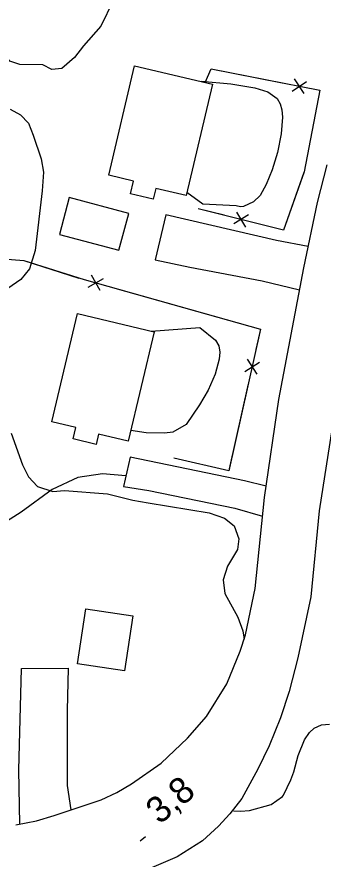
# Model space of a CAD drawing. Extents: x 282461 to 284471, y 5554090 to 5557646.
# Drawn here: x 283239.1 to 283274.2, y 5555299.8 to 5555396.4 of the extents above; entities that cross this region are included whole.
import ezdxf

# ---------------------------------------------------------------- set-up
doc = ezdxf.new("R2010")
doc.units = 0
for name, color, linetype in [('Niveau 1', 7, 'Continuous'), ('Niveau 19', 7, 'Continuous'), ('Niveau 2', 7, 'Continuous'), ('Niveau 21', 7, 'Continuous'), ('Niveau 22', 7, 'Continuous'), ('Niveau 3', 7, 'Continuous'), ('Niveau 31', 7, 'Continuous'), ('Niveau 37', 7, 'Continuous')]:
    doc.layers.add(name, color=color, linetype=linetype)

msp = doc.modelspace()

# ---------------------------------------------------------------- linework, layer by layer
at = {"layer": 'Niveau 1'}
for points in [[(283260.2, 5555389.04), (283263.57, 5555388.73), (283266.32, 5555388.27), (283267.84, 5555387.82), (283268.9, 5555387.04), (283269.24, 5555386.45), (283269.43, 5555385.74), (283269.52, 5555384.92), (283269.33, 5555383.01), (283268.93, 5555380.87), (283268.32, 5555378.87), (283267.64, 5555377.17), (283266.95, 5555375.94), (283266.19, 5555375.2), (283265.02, 5555374.66), (283264.68, 5555374.62), (283264.2, 5555374.76), (283260.36, 5555374.94), (283258.55, 5555376.27)], [(283254.45, 5555360.37), (283260.02, 5555360.79), (283261.84, 5555359.33), (283262.19, 5555358.68), (283262.31, 5555357.96), (283262.26, 5555357.16), (283261.8, 5555355.43), (283260.98, 5555353.59), (283260.01, 5555351.9), (283258.46, 5555349.66), (283256.94, 5555348.78), (283256, 5555348.65), (283253.9, 5555348.71), (283252.11, 5555348.98)]]:
    msp.add_lwpolyline(points, dxfattribs=at)
at = {"layer": 'Niveau 19'}
for points in [[(283272.45, 5555370.07), (283268.81, 5555370.77), (283256.13, 5555373.7), (283254.92, 5555368.53), (283258.87, 5555367.7), (283267.19, 5555366.12), (283271.45, 5555365.11)], [(283267.63, 5555342.57), (283265.16, 5555343.18), (283252.06, 5555345.92), (283251.29, 5555342.55), (283254.2, 5555342.06), (283264.04, 5555340.04), (283267.2, 5555339.13)], [(283239.41, 5555303.82), (283239.29, 5555310), (283239.61, 5555321.66), (283244.95, 5555321.69), (283244.84, 5555316.82), (283244.82, 5555308.24), (283245.26, 5555305.42)]]:
    msp.add_lwpolyline(points, dxfattribs=at)
at = {"layer": 'Niveau 2'}
for points in [[(283250.12, 5555398.26), (283248.7, 5555395.34), (283246.7, 5555393.11), (283245.67, 5555391.77), (283244.24, 5555390.48), (283243.08, 5555390.4), (283242.03, 5555390.91), (283239.41, 5555390.94), (283238.25, 5555391.34), (283237.13, 5555392.89), (283236.63, 5555395.61), (283236.73, 5555396.71)], [(283238.31, 5555385.83), (283239.48, 5555385.2), (283240.42, 5555384.23), (283240.96, 5555382.84), (283241.86, 5555380.13), (283242.11, 5555378.62), (283241.97, 5555376.47), (283241.18, 5555369.62), (283240.51, 5555367.53), (283239.53, 5555366.3), (283237.18, 5555364.65)], [(283238.41, 5555348.66), (283239.73, 5555345.02), (283240.39, 5555343.63), (283241.44, 5555342.54), (283243.19, 5555341.98), (283244.52, 5555342.06), (283249.46, 5555341.7), (283252.37, 5555340.98), (283254.11, 5555340.65), (283261.09, 5555339.51), (283262.84, 5555338.89), (283263.95, 5555338.04), (283264.49, 5555336.53), (283264.33, 5555335.32), (283263.19, 5555333.39), (283262.69, 5555331.82), (283262.88, 5555330.25), (283264.37, 5555327.54), (283264.97, 5555325.99), (283265.12, 5555325.02)], [(283263.9, 5555305.34), (283264.69, 5555305.28), (283265.73, 5555305.35), (283268.22, 5555306.07), (283269.49, 5555306.96), (283269.6, 5555307.13), (283270.45, 5555308.88), (283270.79, 5555309.81), (283271.29, 5555311.67), (283272.02, 5555313.48), (283272.59, 5555314.3), (283273.11, 5555314.82), (283273.97, 5555315.18), (283274.9, 5555315.25)]]:
    msp.add_lwpolyline(points, dxfattribs=at)
at = {"layer": 'Niveau 21'}
for points in [[(283238.96, 5555303.73), (283241.33, 5555304.16), (283243.35, 5555304.77), (283248.73, 5555306.6), (283250.52, 5555307.43), (283252.19, 5555308.43), (283255.59, 5555310.79), (283258.63, 5555313.66), (283260.8, 5555316.15), (283263.13, 5555319.91), (283264.64, 5555323.66), (283265.26, 5555325.53), (283266.36, 5555330.82), (283267.45, 5555341.29), (283269.1, 5555352.52), (283271.93, 5555367.61), (283273.51, 5555375.13), (283274.62, 5555379.43)], [(283276.13, 5555355.43), (283273.72, 5555339.76), (283272.75, 5555329.87), (283271.27, 5555322.87), (283270.27, 5555319.03), (283269.26, 5555316), (283267.97, 5555312.8), (283266.66, 5555310.12), (283264.85, 5555306.73), (283263.48, 5555304.98), (283262.16, 5555303.57), (283260.32, 5555301.87), (283257.44, 5555300.04), (283254.21, 5555298.68)]]:
    msp.add_lwpolyline(points, dxfattribs=at)
at = {"layer": 'Niveau 22'}
msp.add_lwpolyline([(283251.57, 5555343.78), (283248.89, 5555343.98), (283246.06, 5555343.58), (283243.12, 5555342.19), (283239.57, 5555339.61), (283236.69, 5555337.78), (283230.74, 5555335.19), (283227.97, 5555333.53), (283224.88, 5555330.69), (283220.92, 5555327.34), (283219.07, 5555326.16), (283216.12, 5555324.12)], dxfattribs=at)
at = {"layer": 'Niveau 3'}
msp.add_line((283253.18, 5555301.88), (283253.8, 5555302.39), dxfattribs=at)
at = {"layer": 'Niveau 31'}
for points in [[(283261.49, 5555388.71), (283258.45, 5555375.91), (283254.99, 5555376.73), (283254.7, 5555375.49), (283252.09, 5555376.1), (283252.45, 5555377.59), (283249.59, 5555378.26), (283252.53, 5555390.81), (283261.49, 5555388.71)], [(283251.89, 5555373.88), (283245.07, 5555375.68), (283243.95, 5555371.44), (283250.77, 5555369.64), (283251.89, 5555373.88)], [(283243.07, 5555349.96), (283246.03, 5555362.38), (283254.8, 5555360.29), (283251.81, 5555347.73), (283248.42, 5555348.54), (283248.14, 5555347.37), (283245.53, 5555347.99), (283245.84, 5555349.3), (283243.07, 5555349.96)], [(283252.36, 5555327.69), (283251.42, 5555321.38), (283246.01, 5555322.19), (283246.96, 5555328.5), (283252.36, 5555327.69)]]:
    msp.add_lwpolyline(points, dxfattribs=at)
at = {"layer": 'Niveau 37'}
for p, q in [((283270.6, 5555387.91), (283272.26, 5555389.02)), ((283271.99, 5555387.63), (283270.88, 5555389.3)), ((283264.25, 5555374.03), (283265.28, 5555372.31)), ((283265.62, 5555373.69), (283263.91, 5555372.66)), ((283247.23, 5555365.41), (283248.98, 5555366.39)), ((283248.6, 5555365.02), (283247.62, 5555366.77)), ((283265.17, 5555355.75), (283266.86, 5555356.82)), ((283265.47, 5555357.13), (283266.55, 5555355.44))]:
    msp.add_line(p, q, dxfattribs=at)
for points in [[(283260.66, 5555388.9), (283261.34, 5555390.47), (283273.77, 5555388), (283271.97, 5555378.65), (283269.62, 5555371.96), (283259.85, 5555374.4)], [(283260.66, 5555388.9), (283261.34, 5555390.47), (283269.47, 5555388.85)], [(283273.39, 5555388.07), (283273.77, 5555388), (283271.97, 5555378.65), (283271.94, 5555378.56)], [(283271.94, 5555378.56), (283269.62, 5555371.96), (283266.71, 5555372.69)], [(283262.83, 5555373.66), (283259.85, 5555374.4)], [(283236.51, 5555368.72), (283239.88, 5555368.47), (283246.79, 5555366.27), (283266.97, 5555360.58), (283263.34, 5555344.32), (283257.07, 5555345.77)], [(283236.51, 5555368.72), (283239.88, 5555368.47), (283246.19, 5555366.46)], [(283250.03, 5555365.36), (283259.66, 5555362.64)], [(283259.66, 5555362.64), (283266.97, 5555360.58), (283266.45, 5555358.24)], [(283265.58, 5555354.33), (283263.4, 5555344.57)], [(283263.4, 5555344.57), (283263.34, 5555344.32), (283257.07, 5555345.77)]]:
    msp.add_lwpolyline(points, dxfattribs=at)

# ---------------------------------------------------------------- texts
at = {"layer": 'Niveau 3'}
msp.add_text('3,8  ', height=3, rotation=39.56564, dxfattribs=at).set_placement((283255.42, 5555303.68))

doc.saveas('drawing.dxf')
